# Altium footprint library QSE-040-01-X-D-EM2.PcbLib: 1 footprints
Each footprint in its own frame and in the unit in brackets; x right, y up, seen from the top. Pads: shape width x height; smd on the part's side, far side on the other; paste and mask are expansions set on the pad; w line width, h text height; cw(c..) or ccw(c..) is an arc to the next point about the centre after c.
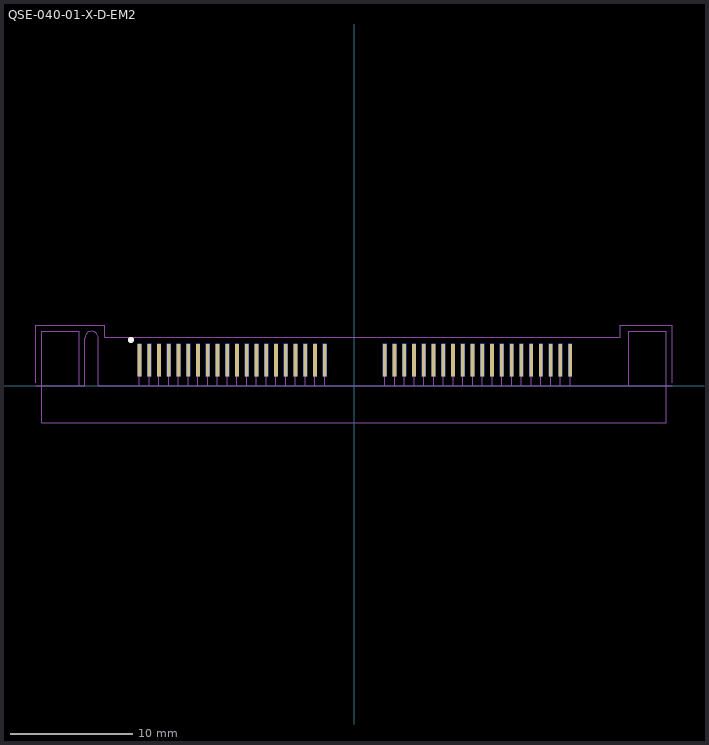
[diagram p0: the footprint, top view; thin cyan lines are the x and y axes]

## QSE-040-01-X-D-EM2 [mil] "0.80mm pitch, 80 pin, high speed socket; w/edge mounts"
height 142.91
pads (80):
  rect 12.01x105 smd far side mask+0: 1(-692.97,82.5) 3(-661.48,82.5) 5(-629.98,82.5) 7(-598.48,82.5) 9(-566.99,82.5) 11(-535.49,82.5) 13(-504,82.5) 15(-472.5,82.5) 17(-441,82.5) 19(-409.51,82.5) 21(-378.01,82.5) 23(-346.52,82.5) 25(-315.02,82.5) 27(-283.52,82.5) 29(-252.03,82.5) 31(-220.53,82.5) 33(-189.04,82.5) 35(-157.54,82.5) 37(-126.04,82.5) 39(-94.55,82.5) 41(99.55,82.5) 43(131.04,82.5) 45(162.54,82.5) 47(194.04,82.5) 49(225.53,82.5) 51(257.03,82.5) 53(288.52,82.5) 55(320.02,82.5) 57(351.52,82.5) 59(383.01,82.5) 61(414.51,82.5) 63(446,82.5) 65(477.5,82.5) 67(509,82.5) 69(540.49,82.5) 71(571.99,82.5) 73(603.48,82.5) 75(634.98,82.5) 77(666.48,82.5) 79(697.97,82.5)
  rect 12.01x105 smd mask+0: 2(-692.97,82.5) 4(-661.48,82.5) 6(-629.98,82.5) 8(-598.48,82.5) 10(-566.99,82.5) 12(-535.49,82.5) 14(-504,82.5) 16(-472.5,82.5) 18(-441,82.5) 20(-409.51,82.5) 22(-378.01,82.5) 24(-346.52,82.5) 26(-315.02,82.5) 28(-283.52,82.5) 30(-252.03,82.5) 32(-220.53,82.5) 34(-189.04,82.5) 36(-157.54,82.5) 38(-126.04,82.5) 40(-94.55,82.5) 42(99.55,82.5) 44(131.04,82.5) 46(162.54,82.5) 48(194.04,82.5) 50(225.53,82.5) 52(257.03,82.5) 54(288.52,82.5) 56(320.02,82.5) 58(351.52,82.5) 60(383.01,82.5) 62(414.51,82.5) 64(446,82.5) 66(477.5,82.5) 68(509,82.5) 70(540.49,82.5) 72(571.99,82.5) 74(603.48,82.5) 76(634.98,82.5) 78(666.48,82.5) 80(697.97,82.5)
Top Overlay:
  circle w9.84: c-720.47,147.64 r4.92
Top Solder:
  lines w5: -692.97,82.5 -692.97,134.98 ; -661.48,82.5 -661.48,134.98 ; -629.98,82.5 -629.98,134.98 ; -598.48,82.5 -598.48,134.98 ; -566.99,82.5 -566.99,134.98 ; -535.49,82.5 -535.49,134.98 ; -504,82.5 -504,134.98 ; -472.5,82.5 -472.5,134.98 ; -441,82.5 -441,134.98 ; -409.51,82.5 -409.51,134.98 ; -378.01,82.5 -378.01,134.98 ; -346.52,82.5 -346.52,134.98 ; -315.02,82.5 -315.02,134.98 ; -283.52,82.5 -283.52,134.98 ; -252.03,82.5 -252.03,134.98 ; -220.53,82.5 -220.53,134.98 ; -189.04,82.5 -189.04,134.98 ; -157.54,82.5 -157.54,134.98 ; -126.04,82.5 -126.04,134.98 ; -94.55,82.5 -94.55,134.98 ; 99.55,82.5 99.55,134.98 ; 131.04,82.5 131.04,134.98 ; 162.54,82.5 162.54,134.98 ; 194.04,82.5 194.04,134.98 ; 225.53,82.5 225.53,134.98 ; 257.03,82.5 257.03,134.98 ; 288.52,82.5 288.52,134.98 ; 320.02,82.5 320.02,134.98 ; 351.52,82.5 351.52,134.98 ; 383.01,82.5 383.01,134.98 ; 414.51,82.5 414.51,134.98 ; 446,82.5 446,134.98 ; 477.5,82.5 477.5,134.98 ; 509,82.5 509,134.98 ; 540.49,82.5 540.49,134.98 ; 571.99,82.5 571.99,134.98 ; 603.48,82.5 603.48,134.98 ; 634.98,82.5 634.98,134.98 ; 666.48,82.5 666.48,134.98 ; 697.97,82.5 697.97,134.98
Bottom Solder:
  lines w5: -692.97,82.5 -692.97,134.98 ; -661.48,82.5 -661.48,134.98 ; -629.98,82.5 -629.98,134.98 ; -598.48,82.5 -598.48,134.98 ; -566.99,82.5 -566.99,134.98 ; -535.49,82.5 -535.49,134.98 ; -504,82.5 -504,134.98 ; -472.5,82.5 -472.5,134.98 ; -441,82.5 -441,134.98 ; -409.51,82.5 -409.51,134.98 ; -378.01,82.5 -378.01,134.98 ; -346.52,82.5 -346.52,134.98 ; -315.02,82.5 -315.02,134.98 ; -283.52,82.5 -283.52,134.98 ; -252.03,82.5 -252.03,134.98 ; -220.53,82.5 -220.53,134.98 ; -189.04,82.5 -189.04,134.98 ; -157.54,82.5 -157.54,134.98 ; -126.04,82.5 -126.04,134.98 ; -94.55,82.5 -94.55,134.98 ; 99.55,82.5 99.55,134.98 ; 131.04,82.5 131.04,134.98 ; 162.54,82.5 162.54,134.98 ; 194.04,82.5 194.04,134.98 ; 225.53,82.5 225.53,134.98 ; 257.03,82.5 257.03,134.98 ; 288.52,82.5 288.52,134.98 ; 320.02,82.5 320.02,134.98 ; 351.52,82.5 351.52,134.98 ; 383.01,82.5 383.01,134.98 ; 414.51,82.5 414.51,134.98 ; 446,82.5 446,134.98 ; 477.5,82.5 477.5,134.98 ; 509,82.5 509,134.98 ; 540.49,82.5 540.49,134.98 ; 571.99,82.5 571.99,134.98 ; 603.48,82.5 603.48,134.98 ; 634.98,82.5 634.98,134.98 ; 666.48,82.5 666.48,134.98 ; 697.97,82.5 697.97,134.98
Mechanical 12:
  lines w0.04: -1027.56,0 -868.96,0 -868.96,153.5 ; -825.96,153.5 -825.96,0 1027.56,0
Mechanical 13:
  circle w9.84: c-720.47,147.64 r4.92
  lines w3.94: -692.97,0 -692.97,82.5 ; -661.48,0 -661.48,82.5 ; -629.98,0 -629.98,82.5 ; -598.48,0 -598.48,82.5 ; -566.99,0 -566.99,82.5 ; -535.49,0 -535.49,82.5 ; -504,0 -504,82.5 ; -472.5,0 -472.5,82.5 ; -441,0 -441,82.5 ; -409.51,0 -409.51,82.5 ; -378.01,0 -378.01,82.5 ; -346.52,0 -346.52,82.5 ; -315.02,0 -315.02,82.5 ; -283.52,0 -283.52,82.5 ; -252.03,0 -252.03,82.5 ; -220.53,0 -220.53,82.5 ; -189.04,0 -189.04,82.5 ; -157.54,0 -157.54,82.5 ; -126.04,0 -126.04,82.5 ; -94.55,0 -94.55,82.5 ; 99.55,0 99.55,82.5 ; 131.04,0 131.04,82.5 ; 162.54,0 162.54,82.5 ; 194.04,0 194.04,82.5 ; 225.53,0 225.53,82.5 ; 257.03,0 257.03,82.5 ; 288.52,0 288.52,82.5 ; 320.02,0 320.02,82.5 ; 351.52,0 351.52,82.5 ; 383.01,0 383.01,82.5 ; 414.51,0 414.51,82.5 ; 446,0 446,82.5 ; 477.5,0 477.5,82.5 ; 509,0 509,82.5 ; 540.49,0 540.49,82.5 ; 571.99,0 571.99,82.5 ; 603.48,0 603.48,82.5 ; 634.98,0 634.98,82.5 ; 666.48,0 666.48,82.5 ; 697.97,0 697.97,82.5 ; -1007.6,-120.08 1007.6,-120.08 1007.6,175 887.6,175 887.6,0 -825.96,0 -825.96,153.5 ccw(c-847.46,153.5) -868.96,153.5 -868.96,0 -887.6,0 -887.6,175 -1007.6,175 -1007.6,-120.08
  text ".Designator" at 0,0 h60
Mechanical 15:
  lines w1.97: -1027.56,9.84 -1027.56,194.88 -805.12,194.88 -805.12,155.51 860.24,155.51 860.24,194.88 1027.56,194.88 1027.56,9.84
Drill Drawing:
  lines w0.04: -868.96,153.5 cw(c-847.46,153.5) -825.96,153.5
